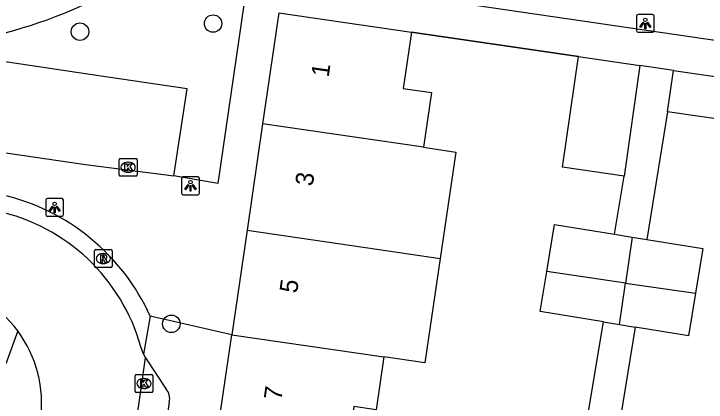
# Model space of a CAD drawing. Extents: x 163686 to 164493, y 382719 to 383870.
# Drawn here: x 164156.03 to 164194.79, y 383025.57 to 383047.3 of the extents above; entities that cross this region are included whole.
import ezdxf

# ---------------------------------------------------------------- set-up
doc = ezdxf.new("R2010")
doc.units = 0
for name, color, linetype in [('IMGEO_Boom', 7, 'Continuous'), ('IMGEO_Kolk', 7, 'Continuous'), ('IMGEO_Lichtpunt', 7, 'Continuous'), ('IMGEO_Muur', 7, 'Continuous'), ('IMGEO_Pand', 7, 'Continuous'), ('IMGEO_Pand_nummerreeks', 7, 'Continuous'), ('IMGEO_Parkeervlak_open', 7, 'Continuous'), ('IMGEO_Rijbaan_lokaal_open', 7, 'Continuous'), ('IMGEO_Rioolput', 7, 'Continuous'), ('IMGEO_Voetpad_halfverhard', 7, 'Continuous'), ('IMGEO_Voetpad_open', 7, 'Continuous')]:
    doc.layers.add(name, color=color, linetype=linetype)

msp = doc.modelspace()

# ---------------------------------------------------------------- linework, layer by layer
at = {"layer": 'IMGEO_Boom'}
for centre in [(164167.183, 383046.756), (164159.731, 383046.3), (164164.844, 383029.95)]:
    msp.add_circle(centre, 0.489, dxfattribs=at)
at = {"layer": 'IMGEO_Kolk'}
for p, q in [((164161.927, 383038.285), (164161.927, 383039.137)), ((164162.002, 383039.211), (164162.854, 383039.211)), ((164162.928, 383039.137), (164162.928, 383038.285)), ((164162.415, 383038.991), (164162.44, 383038.991)), ((164162.438, 383038.431), (164162.413, 383038.431)), ((164162.854, 383038.211), (164162.002, 383038.211)), ((164162.814, 383026.182), (164162.814, 383027.034)), ((164162.889, 383027.108), (164163.741, 383027.108)), ((164163.302, 383026.888), (164163.327, 383026.888)), ((164163.815, 383027.034), (164163.815, 383026.182)), ((164163.741, 383026.108), (164162.889, 383026.108)), ((164163.325, 383026.328), (164163.3, 383026.328))]:
    msp.add_line(p, q, dxfattribs=at)
for points in [[(164161.927, 383038.285), (164161.927, 383039.137)], [(164162.002, 383039.211), (164162.854, 383039.211)], [(164162.928, 383039.137), (164162.928, 383038.285)], [(164162.248, 383038.911), (164162.371, 383038.911), (164162.371, 383038.76), (164162.501, 383038.911), (164162.665, 383038.911), (164162.519, 383038.76), (164162.672, 383038.511), (164162.52, 383038.511), (164162.435, 383038.675), (164162.371, 383038.608), (164162.371, 383038.511), (164162.248, 383038.511), (164162.248, 383038.911)], [(164162.854, 383038.211), (164162.002, 383038.211)], [(164162.814, 383026.182), (164162.814, 383027.034)], [(164162.889, 383027.108), (164163.741, 383027.108)], [(164163.135, 383026.808), (164163.258, 383026.808), (164163.258, 383026.657), (164163.388, 383026.808), (164163.552, 383026.808), (164163.406, 383026.657), (164163.559, 383026.408), (164163.407, 383026.408), (164163.322, 383026.572), (164163.258, 383026.505), (164163.258, 383026.408), (164163.135, 383026.408), (164163.135, 383026.808)], [(164163.815, 383027.034), (164163.815, 383026.182)], [(164163.741, 383026.108), (164162.889, 383026.108)]]:
    msp.add_lwpolyline(points, dxfattribs=at)
for centre, start, end in [((164162.004, 383039.135), 91.552, 178.448), ((164162.004, 383039.135), 91.552, 178.448), ((164162.852, 383039.135), 1.552, 88.448), ((164162.852, 383039.135), 1.552, 88.448), ((164162.004, 383038.287), 181.552, 268.448), ((164162.004, 383038.287), 181.552, 268.448), ((164162.852, 383038.287), 271.552, 358.448), ((164162.852, 383038.287), 271.552, 358.448), ((164162.891, 383027.032), 91.552, 178.448), ((164162.891, 383027.032), 91.552, 178.448), ((164163.739, 383027.032), 1.552, 88.448), ((164163.739, 383027.032), 1.552, 88.448), ((164162.891, 383026.184), 181.552, 268.448), ((164162.891, 383026.184), 181.552, 268.448), ((164163.739, 383026.184), 271.552, 358.448), ((164163.739, 383026.184), 271.552, 358.448)]:
    msp.add_arc(centre, 0.0765, start, end, dxfattribs=at)
for centre, major_axis, ratio, start_param, end_param in [((164162.414, 383038.711), (-0.387, 0.002), 0.722429, 4.712389, 7.853982), ((164162.439, 383038.711), (-0.39, 0.002), 0.717154, 1.570796, 4.712389), ((164163.301, 383026.608), (-0.387, 0.002), 0.722429, 4.712389, 7.853982), ((164163.326, 383026.608), (-0.39, 0.002), 0.717154, 1.570796, 4.712389)]:
    msp.add_ellipse(centre, major_axis=major_axis, ratio=ratio, start_param=start_param, end_param=end_param, dxfattribs=at)
at = {"layer": 'IMGEO_Lichtpunt'}
for p, q in [((164190.887, 383047.167), (164190.887, 383046.36)), ((164190.887, 383047.167), (164190.887, 383046.36)), ((164191.789, 383047.262), (164190.981, 383047.262)), ((164191.789, 383047.262), (164190.981, 383047.262)), ((164191.883, 383046.36), (164191.883, 383047.167)), ((164191.883, 383046.36), (164191.883, 383047.167)), ((164190.981, 383046.266), (164191.789, 383046.266)), ((164190.981, 383046.266), (164191.789, 383046.266)), ((164165.421, 383038.079), (164165.421, 383037.272)), ((164165.421, 383038.079), (164165.421, 383037.272)), ((164166.323, 383038.174), (164165.515, 383038.174)), ((164166.323, 383038.174), (164165.515, 383038.174)), ((164166.417, 383037.272), (164166.417, 383038.079)), ((164166.417, 383037.272), (164166.417, 383038.079)), ((164157.81, 383036.867), (164157.81, 383036.06)), ((164157.81, 383036.867), (164157.81, 383036.06)), ((164158.712, 383036.962), (164157.904, 383036.962)), ((164158.712, 383036.962), (164157.904, 383036.962)), ((164158.806, 383036.06), (164158.806, 383036.867)), ((164158.806, 383036.06), (164158.806, 383036.867)), ((164165.515, 383037.178), (164166.323, 383037.178)), ((164165.515, 383037.178), (164166.323, 383037.178)), ((164157.904, 383035.966), (164158.712, 383035.966)), ((164157.904, 383035.966), (164158.712, 383035.966))]:
    msp.add_line(p, q, dxfattribs=at)
for points in [[(164191.261, 383046.831), (164191.3, 383046.803), (164191.112, 383046.541), (164191.074, 383046.568), (164191.261, 383046.831)], [(164191.363, 383046.783), (164191.41, 383046.783), (164191.41, 383046.461), (164191.363, 383046.461), (164191.363, 383046.783)], [(164191.473, 383046.803), (164191.511, 383046.83), (164191.698, 383046.568), (164191.659, 383046.54), (164191.473, 383046.803)], [(164165.795, 383037.743), (164165.834, 383037.715), (164165.646, 383037.453), (164165.608, 383037.48), (164165.795, 383037.743)], [(164165.897, 383037.695), (164165.944, 383037.695), (164165.944, 383037.373), (164165.897, 383037.373), (164165.897, 383037.695)], [(164166.007, 383037.715), (164166.045, 383037.742), (164166.232, 383037.48), (164166.193, 383037.452), (164166.007, 383037.715)], [(164158.184, 383036.531), (164158.223, 383036.503), (164158.035, 383036.241), (164157.997, 383036.268), (164158.184, 383036.531)], [(164158.286, 383036.483), (164158.333, 383036.483), (164158.333, 383036.161), (164158.286, 383036.161), (164158.286, 383036.483)], [(164158.396, 383036.503), (164158.434, 383036.53), (164158.621, 383036.268), (164158.582, 383036.24), (164158.396, 383036.503)]]:
    msp.add_lwpolyline(points, dxfattribs=at)
for centre in [(164191.386, 383046.965), (164165.92, 383037.877), (164158.309, 383036.665)]:
    msp.add_circle(centre, 0.0994, dxfattribs=at)
for centre, start, end in [((164190.981, 383047.167), 90, 180), ((164190.981, 383047.167), 90, 180), ((164191.789, 383047.167), 0, 90), ((164191.789, 383047.167), 0, 90), ((164190.981, 383046.36), 180, 270), ((164190.981, 383046.36), 180, 270), ((164191.789, 383046.36), 270, 0), ((164191.789, 383046.36), 270, 360), ((164165.515, 383038.079), 90, 180), ((164165.515, 383038.079), 90, 180), ((164166.323, 383038.079), 0, 90), ((164166.323, 383038.079), 0, 90), ((164165.515, 383037.272), 180, 270), ((164165.515, 383037.272), 180, 270), ((164166.323, 383037.272), 270, 0), ((164166.323, 383037.272), 270, 360), ((164157.904, 383036.867), 90, 180), ((164157.904, 383036.867), 90, 180), ((164158.712, 383036.867), 0, 90), ((164158.712, 383036.867), 0, 90), ((164157.904, 383036.06), 180, 270), ((164157.904, 383036.06), 180, 270), ((164158.712, 383036.06), 270, 0), ((164158.712, 383036.06), 270, 360)]:
    msp.add_arc(centre, 0.0946, start, end, dxfattribs=at)
at = {"layer": 'IMGEO_Muur'}
msp.add_lwpolyline([(164178.286, 383046.267), (164187.643, 383044.904)], dxfattribs=at)
at = {"layer": 'IMGEO_Pand'}
for points in [[(164170.868, 383047.353), (164169.96, 383041.146)], [(164170.868, 383047.353), (164178.286, 383046.267)], [(164178.286, 383046.267), (164177.826, 383043.127), (164179.41, 383042.896), (164178.963, 383039.83)], [(164190.198, 383038.22), (164186.752, 383038.717), (164187.643, 383044.904)], [(164187.643, 383044.904), (164191.089, 383044.406)], [(164191.089, 383044.406), (164190.198, 383038.22)], [(164192.634, 383041.819), (164192.969, 383044.135)], [(164192.969, 383044.135), (164196.589, 383043.612)], [(164196.589, 383043.612), (164196.255, 383041.296), (164192.634, 383041.819)], [(164169.96, 383041.146), (164169.088, 383035.191)], [(164178.963, 383039.83), (164169.96, 383041.146)], [(164178.963, 383039.83), (164180.777, 383039.565), (164179.906, 383033.61)], [(164185.865, 383032.877), (164186.297, 383035.515), (164189.666, 383034.964)], [(164169.088, 383035.191), (164168.232, 383029.342)], [(164169.088, 383035.191), (164176.354, 383034.129), (164179.906, 383033.61)], [(164189.666, 383034.964), (164190.651, 383034.803)], [(164190.651, 383034.803), (164190.275, 383032.23)], [(164190.651, 383034.803), (164191.466, 383034.67)], [(164191.466, 383034.67), (164194.605, 383034.157), (164194.197, 383031.656)], [(164179.906, 383033.61), (164179.05, 383027.76), (164176.74, 383028.098)], [(164189.041, 383030.054), (164185.499, 383030.634), (164185.865, 383032.877)], [(164190.275, 383032.23), (164185.865, 383032.877)], [(164189.936, 383029.908), (164190.275, 383032.23)], [(164190.275, 383032.23), (164194.197, 383031.656)], [(164194.197, 383031.656), (164193.807, 383029.275), (164190.825, 383029.763)], [(164189.041, 383030.054), (164189.936, 383029.908)], [(164189.936, 383029.908), (164190.825, 383029.763)], [(164167.356, 383023.354), (164168.232, 383029.342)], [(164168.232, 383029.342), (164176.74, 383028.098)], [(164176.74, 383028.098), (164176.307, 383025.136), (164175.072, 383025.316), (164174.629, 383022.291)]]:
    msp.add_lwpolyline(points, dxfattribs=at)
at = {"layer": 'IMGEO_Parkeervlak_open'}
msp.add_lwpolyline([(164164.98, 383038.234), (164165.739, 383043.108), (164160.791, 383043.822), (164155.662, 383044.603), (164153.2, 383044.955)], dxfattribs=at)
at = {"layer": 'IMGEO_Rijbaan_lokaal_open'}
for points in [[(164163.295, 383028.249), (164163.138, 383028.667)], [(164162.802, 383023.844), (164163.154, 383026.331), (164163.395, 383028.038)], [(164163.295, 383028.249), (164163.395, 383028.038)]]:
    msp.add_lwpolyline(points, dxfattribs=at)
for centre, radius, start, end in [((164152.794, 383025.762), 10.745, 15.6879, 77.6597), ((164150.868, 383025.533), 6.711, 36.8003, 81.656), ((164150.869, 383025.534), 6.71, 351.9263, 36.792)]:
    msp.add_arc(centre, radius, start, end, dxfattribs=at)
at = {"layer": 'IMGEO_Rioolput'}
for p, q in [((164160.612, 383034.1), (164161.464, 383034.1)), ((164160.537, 383033.174), (164160.537, 383034.026)), ((164161.025, 383033.88), (164161.05, 383033.88)), ((164161.538, 383034.026), (164161.538, 383033.174)), ((164161.048, 383033.32), (164161.023, 383033.32)), ((164161.464, 383033.1), (164160.612, 383033.1))]:
    msp.add_line(p, q, dxfattribs=at)
for points in [[(164160.612, 383034.1), (164161.464, 383034.1)], [(164160.537, 383033.174), (164160.537, 383034.026)], [(164161.126, 383033.798), (164160.874, 383033.8), (164160.874, 383033.4)], [(164161.052, 383033.719), (164160.998, 383033.719), (164160.998, 383033.638)], [(164161.538, 383034.026), (164161.538, 383033.174)], [(164160.874, 383033.4), (164160.998, 383033.4), (164160.998, 383033.562), (164161.009, 383033.562)], [(164160.998, 383033.638), (164161.05, 383033.638)], [(164161.056, 383033.533), (164161.127, 383033.4), (164161.267, 383033.4), (164161.202, 383033.526)], [(164161.464, 383033.1), (164160.612, 383033.1)]]:
    msp.add_lwpolyline(points, dxfattribs=at)
for centre, radius, start, end in [((164160.614, 383034.024), 0.0765, 91.552, 178.448), ((164160.614, 383034.024), 0.0765, 91.552, 178.448), ((164161.462, 383034.024), 0.0765, 1.552, 88.448), ((164161.462, 383034.024), 0.0765, 1.552, 88.448), ((164161.058, 383033.623), 0.0964, 77.0061, 93.1865), ((164161.072, 383033.68), 0.0378, 276.6634, 79.6772), ((164161.125, 383033.688), 0.109, 350.3612, 89.416), ((164161.008, 383033.509), 0.0533, 26.0293, 88.6989), ((164161.034, 383033.827), 0.19, 274.7715, 282.9687), ((164161.123, 383033.688), 0.112, 277.5842, 350.9817), ((164161.107, 383033.473), 0.108, 29.5134, 73.7905), ((164160.614, 383033.176), 0.0765, 181.552, 268.448), ((164160.614, 383033.176), 0.0765, 181.552, 268.448), ((164161.462, 383033.176), 0.0765, 271.552, 358.448), ((164161.462, 383033.176), 0.0765, 271.552, 358.448)]:
    msp.add_arc(centre, radius, start, end, dxfattribs=at)
for centre, major_axis, ratio, start_param, end_param in [((164161.024, 383033.6), (-0.387, 0.002), 0.722429, 4.712389, 7.853982), ((164161.049, 383033.6), (-0.39, 0.002), 0.717154, 1.570796, 4.712389)]:
    msp.add_ellipse(centre, major_axis=major_axis, ratio=ratio, start_param=start_param, end_param=end_param, dxfattribs=at)
at = {"layer": 'IMGEO_Voetpad_halfverhard'}
msp.add_arc((164148.762, 383072.184), 26.814, 280.4586, 297.2622, dxfattribs=at)
at = {"layer": 'IMGEO_Voetpad_open'}
for points in [[(164170.675, 383049.429), (164170.738, 383049.419), (164217.162, 383042.632)], [(164168.897, 383047.801), (164167.449, 383037.807), (164164.98, 383038.234)], [(164187.643, 383044.904), (164178.286, 383046.267)], [(164192.969, 383044.135), (164191.089, 383044.406)], [(164192.634, 383041.819), (164191.466, 383034.67)], [(164152.624, 383041.139), (164152.452, 383039.999), (164154.923, 383039.607), (164160.032, 383038.872), (164164.98, 383038.234)], [(164189.666, 383034.964), (164190.198, 383038.22)], [(164163.661, 383030.372), (164163.295, 383028.249)], [(164168.232, 383029.342), (164163.661, 383030.372)], [(164187.907, 383023.247), (164189.041, 383030.054)], [(164156.242, 383029.553), (164155.571, 383027.702)], [(164190.825, 383029.763), (164189.72, 383023.007)], [(164163.395, 383028.038), (164164.556, 383026.298)], [(164164.729, 383025.565), (164163.977, 383020.366), (164163.593, 383017.725)]]:
    msp.add_lwpolyline(points, dxfattribs=at)
for centre, radius, start, end in [((164152.677, 383025.424), 12.047, 24.2516, 76.9184), ((164163.946, 383025.767), 0.809, 345.5293, 41.0302)]:
    msp.add_arc(centre, radius, start, end, dxfattribs=at)

# ---------------------------------------------------------------- texts
at = {"layer": 'IMGEO_Pand_nummerreeks'}
for s, rotation, p in [('1', 81.6743, (164173.652, 383043.722)), ('3', 81.6751, (164172.758, 383037.619)), ('5', 81.6751, (164171.881, 383031.627)), ('7', 81.6743, (164171.006, 383025.634))]:
    msp.add_text(s, height=1, rotation=rotation, dxfattribs=at).set_placement(p)

doc.saveas('drawing.dxf')
